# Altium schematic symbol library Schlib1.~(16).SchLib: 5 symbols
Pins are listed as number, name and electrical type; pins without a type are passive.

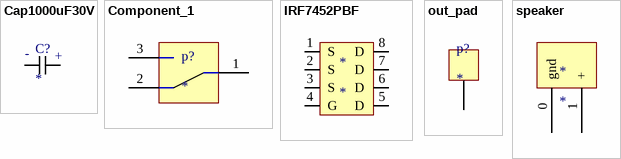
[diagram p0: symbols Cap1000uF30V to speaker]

## Cap1000uF30V
designator C?
Capasitance: 1000uF; Voltage: 30V
footprint Cap_1000uF_35V - duplicate
pins: 1 3, 2 -

## Component_1
designator p?
pins: 1 in, 2, 3

## IRF7452PBF
designator *
footprint SO-8_M (Footprint not found)
pins: 1 S, 2 S, 3 S, 4 G, 5 D, 6 D, 7 D, 8 D

## out_pad
designator p?
footprint pad
pins: 0

## speaker
designator *
footprint speaker
pins: 0 gnd, 1 +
